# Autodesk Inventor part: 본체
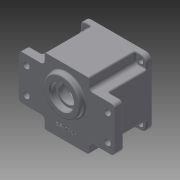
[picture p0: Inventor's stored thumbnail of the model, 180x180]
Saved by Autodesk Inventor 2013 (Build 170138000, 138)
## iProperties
Created: 2015-07
Part Number: 본체
Material: 일반
Document SubType Name: Modeling
Designer: user
Density: 1 g/cm^3
Author: user
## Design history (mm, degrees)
sketch "스케치1"
  geometry: L1 (65, -30)-(-65, -30); L2 (-65, -30)-(-65, 30); L3 (-65, 30)-(65, 30); L4 (65, 30)-(65, -30); L5 (65, -30)-(-65, 30); L6 (-65, -30)-(65, 30); L7 (45, -45)-(-45, -45); L8 (-45, -45)-(-45, 45); L9 (-45, 45)-(45, 45); L10 (45, 45)-(45, -45); L11 (45, -45)-(-45, 45); L12 (-45, -45)-(45, 45); 1 further point
  constraints: 24 end point, 4 midpoint, 4 parallel, 2 horizontal, 2 perpendicular
  dimensions: "d0" = 130 distance of L2.end L3.end; "d1" = 60 distance of L1.end L2.end; "d2" = 90 distance of L8.end L9.end; "d3" = 90 distance of L7.end L8.end
extrude "돌출1" new body sketch "스케치1" distance "d4" = 12; taper "d5" = 0 deg
sketch "스케치2"
  geometry: L1 (45, -45)-(-45, -45); L2 (-45, -45)-(-45, 45); L3 (-45, 45)-(45, 45); L4 (45, 45)-(45, -45); L5 (45, -45)-(-45, 45); L6 (-45, -45)-(45, 45); 1 further point
  constraints: 12 end point, 2 midpoint, 2 parallel, 1 horizontal, 1 perpendicular
  dimensions: "d6" = 90 distance of L2.end L3.end (derived); "d7" = 90 distance of L1.end L2.end (derived)
extrude "돌출2" join sketch "스케치2" distance "d8" = 58; taper "d9" = 0 deg
sketch "스케치3"
  geometry: L1 (45, 30)-(45, 45) reference; L2 (45, 45)-(-45, 45) reference; L3 (-45, 45)-(-45, 30) reference; L4 (-45, -30)-(-45, -45) reference; L5 (30, -30)-(-30, -30); L6 (-30, -30)-(-30, 30); L7 (-30, 30)-(30, 30); L8 (30, 30)-(30, -30); L9 (30, -30)-(-30, 30); L10 (-30, -30)-(30, 30); L11 (-30, 30)-(-45, 30); L12 (30, 30)-(45, 30); L13 (30, 30)-(30, 45); L14 (-30, 30)-(-30, 45); L15 (-30, 45)-(-45, 45); L16 (-45, 30)-(-45, 45); L17 (30, 45)-(45, 45); L18 (45, 45)-(45, 30); L19 (0, 0)-(41.753, 0); L20 (-30, -30)-(-30, -45); L21 (-30, -30)-(-45, -30); L22 (-45, -30)-(-45, -45); L23 (-30, -45)-(-45, -45); L24 (30, -45)-(45, -45); L25 (30, -30)-(30, -45); L26 (30, -30)-(45, -30); L27 (45, -45)-(45, -30)
  constraints: 46 end point, 6 perpendicular, 2 collinear, 2 midpoint, 2 parallel, 2 point on line, 2 symmetric about line, 1 horizontal
  dimensions: "d10" = 60 distance of L6.end L7.end; "d11" = 60 distance of L5.end L6.end
extrude "돌출3" cut sketch "스케치3" distance "d12" = 63; taper "d13" = 0 deg
sketch "스케치4"
  geometry: L1 (37, -37)-(-37, -37); L2 (-37, -37)-(-37, 37); L3 (-37, 37)-(37, 37); L4 (37, 37)-(37, -37); L5 (37, -37)-(-37, 37); L6 (-37, -37)-(37, 37); C1 r 3.5 at (-37, 37); C2 r 3.5 at (-37, -37); C3 r 3.5 at (37, -37); C4 r 3.5 at (37, 37); 1 further point
  constraints: 12 end point, 4 centre point, 2 midpoint, 2 parallel, 1 coincident, 1 horizontal, 1 perpendicular, 9 other
  dimensions: "d14" = 74 distance of L2.end L3.end; "d15" = 74 distance of L1.end L2.end; "d16" = 7 diameter of C1; "d19" = 360 deg dimension on point (0, 0) C1.centre (derived)
extrude "돌출4" cut sketch "스케치4" distance "d21" = 63; taper "d22" = 0 deg
fillet "모깎기1" dims "d23" = 8
fillet "모깎기2" dims "d24" = 8
sketch "스케치5"
  geometry: C1 r 40 at (0, 0); 1 further point
  constraints: 1 centre point, 1 coincident
  dimensions: "d25" = 80 diameter of C1
extrude "돌출5" cut sketch "스케치5" distance "d26" = 9; taper "d27" = 0 deg
sketch "스케치6"
  geometry: C1 r 40 at (0, 0) reference; C2 r 39 at (0, 0)
  constraints: 1 centre point, 1 coincident
  dimensions: "d28" = 78 diameter of C2
extrude "돌출6" cut sketch "스케치6" distance "d29" = 52; taper "d30" = 0 deg
sketch "스케치7"
  geometry: L1 (-65, -30)-(-30, -30) reference; L2 (0, 0)-(0, 11); C1 r 25 at (0, 11)
  constraints: 2 end point, 1 centre point, 1 coincident, 1 perpendicular
  dimensions: "d31" = 11 distance of L2.start L2.end; "d32" = 50 diameter of C1
extrude "돌출7" join sketch "스케치7" distance "d33" = 7; taper "d34" = 0 deg
sketch "스케치8"
  geometry: C1 r 25 at (0, 0) reference; C2 r 16 at (0, 0); 1 further point
  constraints: 1 centre point, 1 coincident
  dimensions: "d35" = 32 diameter of C2
extrude "돌출8" cut sketch "스케치8" distance "d36" = 8; taper "d37" = 0 deg
sketch "스케치9"
  geometry: L1 (0, 0)-(0, -11); L2 (0, 0)-(0, 20); C1 r 39 at (0, 0) reference; A1 r 20.5 centre (0, -11) between (-7.402, 8.117) and (7.402, 8.117); A2 r 14 centre (0, 20) between (7.402, 8.117) and (-7.402, 8.117)
  constraints: 4 end point, 4 point on circle, 2 centre point, 1 coincident, 1 collinear, 1 vertical
  dimensions: "d38" = 11 distance of L1.start L1.end; "d39" = 41 diameter of A1; "d40" = 20 distance of L1.start L2.end; "d41" = 28 diameter of A2; "d42" = 7.40221 distance from line of A1.end L1; "d43" = 0 distance from line of A2.centre L1
extrude "돌출9" join sketch "스케치9" distance "d44" = 7; taper "d45" = 0 deg
sketch "스케치10"
  geometry: C1 r 16 at (0, 0) reference; C2 r 12.5 at (0, 0); 1 further point
  constraints: 1 centre point, 1 coincident
  dimensions: "d46" = 25 diameter of C2
extrude "돌출10" cut sketch "스케치10" distance "d47" = 5; taper "d48" = 0 deg
sketch "스케치11"
  geometry: C1 r 12.5 at (0, 0) reference; C2 r 17.5 at (0, 0); 1 further point
  constraints: 1 centre point, 1 coincident
  dimensions: "d49" = 35 diameter of C2
extrude "돌출11" cut sketch "스케치11" distance "d50" = 10; taper "d51" = 0 deg
sketch "스케치12"
  geometry: C1 r 11 at (0, 20); A1 r 14 centre (0, 20) between (7.402, 8.117) and (-7.402, 8.117) reference; 1 further point
  constraints: 1 centre point, 1 coincident
  dimensions: "d52" = 22 diameter of C1
extrude "돌출12" cut sketch "스케치12" distance "d53" = 7; taper "d54" = 0 deg
sketch "스케치13"
  geometry: C1 r 11 at (0, 0) reference; C2 r 9.5 at (0, 0); 1 further point
  constraints: 1 centre point, 1 coincident
  dimensions: "d55" = 19 diameter of C2
extrude "돌출13" cut sketch "스케치13" distance "d56" = 1; taper "d57" = 0 deg
sketch "스케치14"
  geometry: L1 (55, -17.5)-(-55, -17.5); L2 (-55, -17.5)-(-55, 17.5); L3 (-55, 17.5)-(55, 17.5); L4 (55, 17.5)-(55, -17.5); L5 (55, -17.5)-(-55, 17.5); L6 (-55, -17.5)-(55, 17.5); C1 r 4.5 at (55, 17.5); C2 r 4.5 at (55, -17.5); C3 r 4.5 at (-55, -17.5); C4 r 4.5 at (-55, 17.5); 1 further point
  constraints: 12 end point, 4 centre point, 4 coincident, 2 midpoint, 2 parallel, 1 horizontal, 1 perpendicular
  dimensions: "d58" = 110 distance of L2.end L3.end; "d59" = 35 distance of L1.end L2.end; "d60" = 9 diameter of C1; "d61" = 9 diameter of C2; "d62" = 9 diameter of C3; "d63" = 9 diameter of C4
extrude "돌출14" cut sketch "스케치14" distance "d64" = 12; taper "d65" = 0 deg
sketch "스케치16"
  geometry: L1 (0, 0)-(35, 0); L2 (0, 0)-(21.92, 21.92); C1 r 39 at (0, 0) reference; A1 r 39 centre (0, 0) between (32.777, 21.134) and (21.134, 32.777); A2 r 35 centre (0, 0) between (21.763, 27.411) and (27.411, 21.763); A3 r 4 centre (24.749, 24.749) between (21.809, 27.462) and (27.462, 21.809); A4 r 3.5 centre (29.836, 19.238) between (32.777, 21.134) and (27.412, 21.762); A5 r 3.5 centre (19.238, 29.836) between (21.762, 27.412) and (21.134, 32.777)
  constraints: 18 point on circle, 5 centre point, 5 tangent, 4 end point, 2 coincident, 1 horizontal
  dimensions: "d78" = 78 diameter of A1; "d79" = 70 diameter of A2; "d80" = 45 deg angle of L2 L1; "d81" = 8 diameter of A3; "d82" = 7 diameter of A4; "d84" = 7 diameter of A5; "d85" = 21.13421 distance from line of A1.start L1
extrude "돌출16" join sketch "스케치16" distance "d86" = 52; taper "d87" = 0 deg
fillet "모깎기3" dims "d91" = 5
fillet "모깎기6" dims "d94" = 2
sketch "스케치17"
  geometry: A1 r 4 centre (24.749, -24.749) between (27.462, -21.809) and (21.809, -27.462) reference; A2 r 4 centre (-24.749, -24.749) between (-21.809, -27.462) and (-27.462, -21.809) reference; A3 r 4 centre (-24.749, 24.749) between (-27.462, 21.809) and (-21.809, 27.462) reference; A4 r 4 centre (24.749, 24.749) between (21.809, 27.462) and (27.462, 21.809) reference
hole "구멍1" sketch "스케치17" at (-24.749, 24.749), (-24.749, -24.749), (24.749, 24.749), (24.749, -24.749) diameter "d96" = 3.459; stored, may be unused: countersink angle "d100" = 90 deg, drill point angle "d102" = 118 deg; dims "d97" = 12, "d98" = 4, "d99" = 2, "d101" = 15
fillet "모깎기8" dims "d103" = 2
fillet "모깎기9" dims "d104" = 3
fillet "모깎기10" dims "d105" = 2
chamfer "모따기1" distance "d106" = 1; stored, may be unused: second distance "d107" = 2, angle "d108" = 45 deg
fillet "모깎기11" dims "d109" = 0.3
fillet "모깎기12" dims "d110" = 2
fillet "모깎기13" dims "d111" = 5
sketch "스케치18"
  geometry: L1 (-30, -45)-(30, -45) reference; 4 further points
  constraints: 1 other
  dimensions: "d114" = 0 horizontal distance of point (0, 0) point (0, -30); "d115" = 15 distance from line of L1 point (0, -30)
feature "엠보싱1" sketch "스케치18" dims "d116" = 0.5, "d117" = 0
fillet "모깎기21" dims "d123" = 2
fillet "모깎기24" dims "d126" = 2
fillet "모깎기26" dims "d128" = 2
fillet "모깎기27" dims "d129" = 2
fillet "모깎기28" dims "d130" = 2
fillet "모깎기29" dims "d131" = 2
chamfer "모따기2" distance "d132" = 1; stored, may be unused: second distance "d133" = 2, angle "d134" = 45 deg
node "솔리드1"
pattern_circular "원형 패턴1" dims angle "d89" = 360 deg
